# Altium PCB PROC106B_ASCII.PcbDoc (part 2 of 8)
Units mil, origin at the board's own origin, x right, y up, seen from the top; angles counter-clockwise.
Board outline 4498.18 x 1060.53 mil, 8 copper layers (Top Layer, GND1, Sig1, PWR1, PWR2, Sig2, GND2, Bottom Layer), stack 69.602 mil thick; 439 components, 327 nets, 1548 pads, 843 vias.
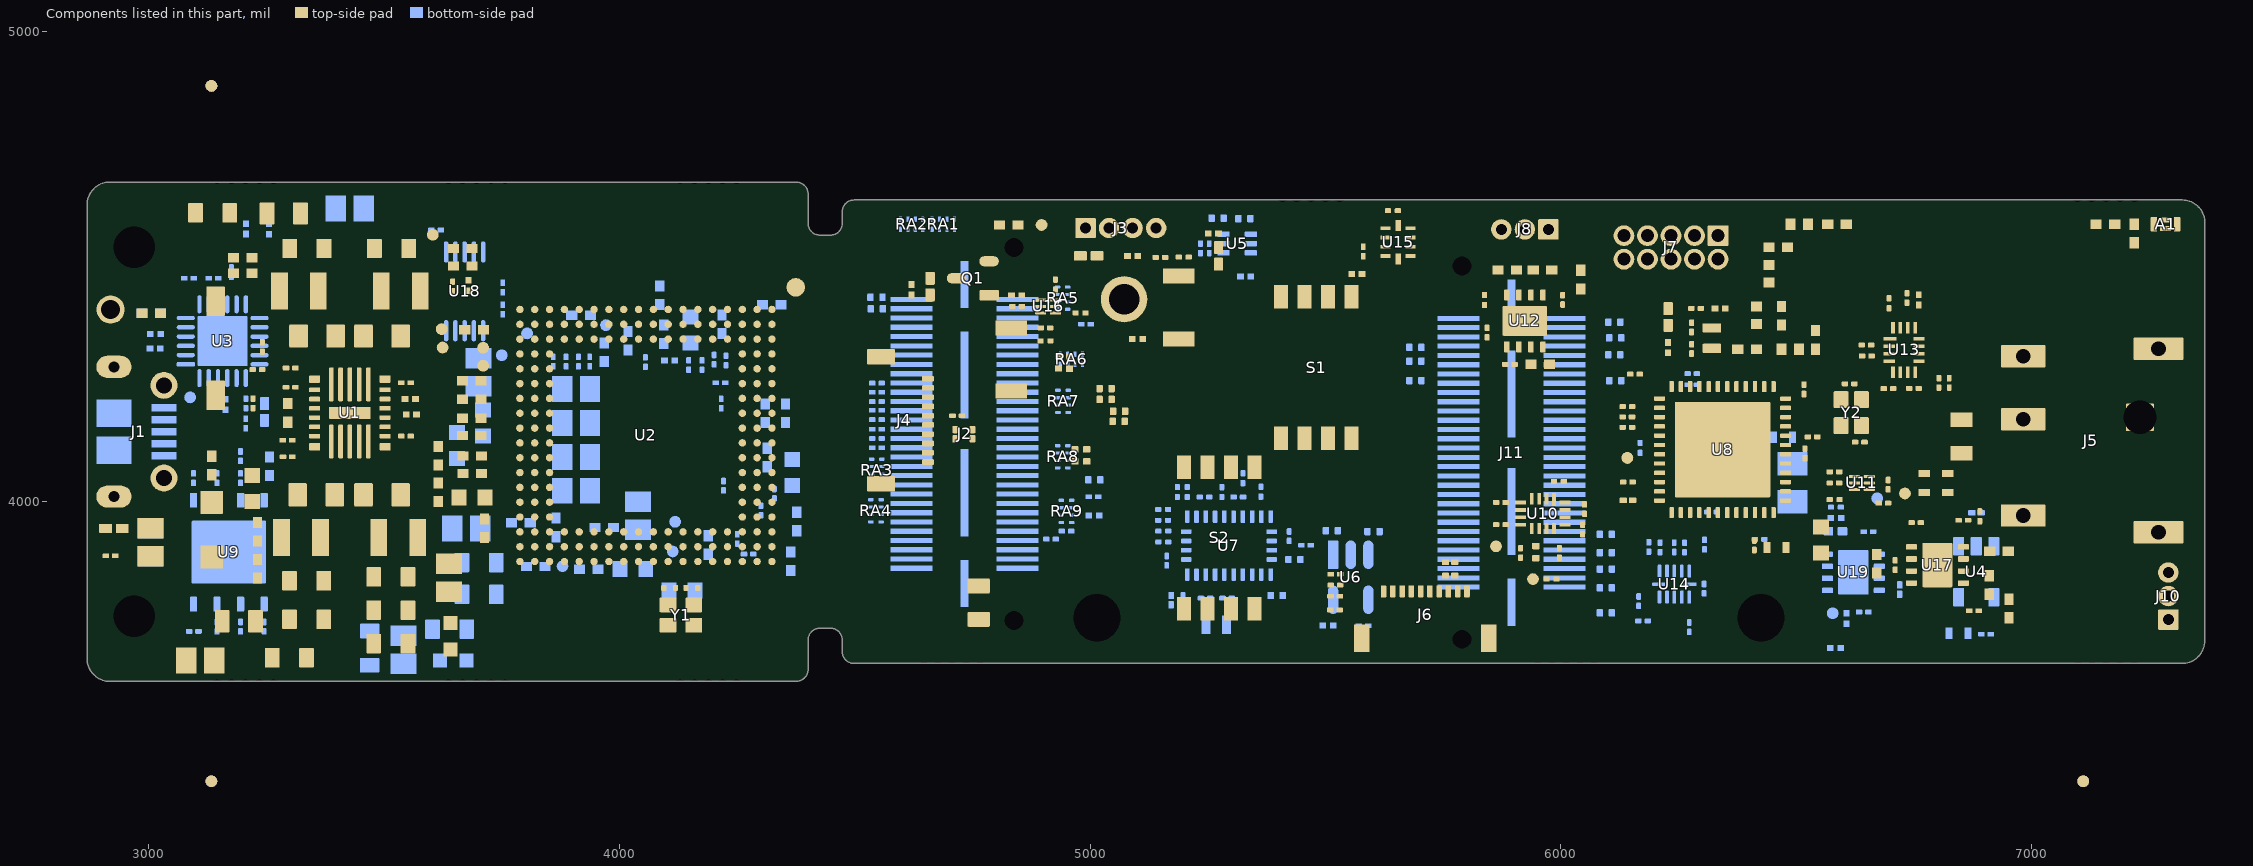
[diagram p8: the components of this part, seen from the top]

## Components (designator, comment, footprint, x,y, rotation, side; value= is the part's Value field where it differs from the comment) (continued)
C125 "CL03A103KA3NNNC" FP-CL03A103KA3NNNC_0201-IPC_C 5252.95,4538.7 r270 bottom
C126 "GCM155R71C104KA55D" 0402L 3691.38,4365.53 r180 top
C127 "GRM033R6YA104KE14D" "FP-GRM033R6YA104KE14D_0201 (0603 Metric)-IPC_C" 6653.18,3936.75 r180 bottom
C128 "GRM033R6YA104KE14D" "FP-GRM033R6YA104KE14D_0201 (0603 Metric)-IPC_C" 6643.28,3766.12 r180 bottom
C129 "CL03A105MO3NRNH" FP-CL03A105MO3NRNH_0201-IPC_C 6719.58,3813.74 r270 bottom
C130 "GCM155R71C104KA55D" 0402L 3967.83,4318.05 r90 bottom
C131 "CGA4J1X7T0J226M125AC" FP-CGA4J1X7T0J226M125AC_0805-MFG 3469.55,3689.64 r90 bottom
D1 "NRVB230LSFT1G" FP-NRVB230LSFT1G_SOD-123F-MFG 3134.01,3940.99 r90 top
Designator1 "Comment" MHNP_M2_PANHEAD_PHILLIPS 2983.52,4883.72 r0 top
Designator1_1 "BRAKE_WAY_HOLES1X2" BRAKE_WAY_HOLES1X2 3205.41,3572.64 r180 bottom
Designator1_2 "Comment" MHNP_M2_PANHEAD_PHILLIPS 2969.58,4541.42 r0 top
Designator2 "BRAKE_WAY_HOLES1X2" BRAKE_WAY_HOLES1X2 4188.97,4725.69 r180 top
Designator2_1 "BRAKE_WAY_HOLES1X2" BRAKE_WAY_HOLES1X2 6010.52,3609.79 r180 bottom
Designator3 "BRAKE_WAY_HOLES1X2" BRAKE_WAY_HOLES1X2 3697.19,4725.69 r180 top
Designator3_2 "BRAKE_WAY_HOLES1X2" BRAKE_WAY_HOLES1X2 5469.11,4687.74 r0 bottom
Designator4 "BRAKE_WAY_HOLES1X2" BRAKE_WAY_HOLES1X2 4706.5,3609.79 r0 top
Designator4_1 "BRAKE_WAY_HOLES1X2" BRAKE_WAY_HOLES1X2 3697.19,3572.64 r180 bottom
Designator5 "BRAKE_WAY_HOLES1X2" BRAKE_WAY_HOLES1X2 7157.87,4687.69 r180 top
Designator5_1 "BRAKE_WAY_HOLES1X2" BRAKE_WAY_HOLES1X2 7157.6,3609.79 r180 bottom
Designator5_2 "BRAKE_WAY_HOLES1X2" BRAKE_WAY_HOLES1X2 4188.97,3572.64 r180 bottom
Designator6 "Comment" MHNP_M2_PANHEAD_PHILLIPS 7259.4,4883.72 r0 top
Designator7 "Comment" MHNP_M2_PANHEAD_PHILLIPS 2983.52,3406.7 r0 top
Designator7_1 "Comment" MHNP_M2_PANHEAD_PHILLIPS 2969.58,3756.91 r0 top
Designator8 "Comment" MHNP_M2_PANHEAD_PHILLIPS 7259.4,3406.7 r0 top
Designator10 "BRAKE_WAY_HOLES1X2" BRAKE_WAY_HOLES1X2 3205.41,4725.69 r180 top
Designator22_1 "Comment" MHNP_2-5 6425,3754.06 r0 bottom
Designator23 "Comment" MHNP_2-5 5014.62,3754.06 r0 bottom
FID1 "Fiducial" FIDUCIAL6.4-20 3133.52,3406.7 r0 top
FID2 "Fiducial" FIDUCIAL6.4-20 3133.52,4883.72 r0 top
FID3 "Fiducial" FIDUCIAL6.4-20 7109.4,3406.7 r0 top
FID4 "Fiducial" FIDUCIAL6.4-20 7109.4,3406.7 r180 bottom
FID5 "Fiducial" FIDUCIAL6.4-20 3133.52,4883.72 r180 bottom
FID6 "Fiducial" FIDUCIAL6.4-20 3133.52,3406.7 r180 bottom
FL2 "BLM15PD300SZ1D" 0402L 3134.06,4077.41 r270 top
FL3 "BLM15PD300SZ1D" 0402L 6670.79,3868.56 r90 top
FL12 "BLM15PD300SZ1D" 0402L 5955.92,4292.41 r0 top
FL22 "BLM15PD300SZ1D" 0402L 4827.36,4588.36 r0 top
J1 "105017-0001" CONN_105017-0001 2979.51,4149.15 r90 bottom
J2 "QSH-030-01-L-D-A" Samtec_QSH-030-01-X-D-A 4733.36,4144.5 r0 bottom locked
J3 "M50-3930442" FP-M50-3930442_HDR4-RECOMMENDED_LAND_PATTERN 5065.29,4621.12 r0 bottom
J4 "51441-1093" FP-51441-1093_CONN_SMD_FFC-0 4585.45,4173.34 r270 top locked
J5 "PJ-051AH" CUI_PJ-051AH 7229.96,4179.69 r0 top
J6 "51441-1093" FP-51441-1093_CONN_SMD_FFC-0 5711.91,3740.17 r0 top
J7 "GRPB052MWCN-RC" FP-GRPB052MWCN-RC_HDR10-MFG 6233.84,4610.83 r180 top
J8 "M50-3930342" FP-M50-3930342_HDR3-MFG 5923.44,4618.25 r180 top
J10 "M50-3930342" FP-M50-3930342_HDR3-MFG 7329.6,3800 r90 top
J11 "QSH-030-01-L-D-A" Samtec_QSH-030-01-X-D-A 5895.12,4104.5 r180 bottom locked
L1 "LQG15HS2N4S02D" IND_LQG15H 6487.22,4324.41 r0 top
L2 "DFE252012PD-R47M" DFE252012P 3535.79,4447.85 r180 top
L3 "DFE252012PD-R47M" DFE252012P 3319.27,4447.85 r0 top
L4 "DFE252012PD-R47M" DFE252012P 3530.36,3924.63 r180 top
L5 "DFE252012PD-R47M" DFE252012P 3323.75,3924.63 r0 top
L6 "LQG15HS2N4S02D" IND_LQG15H 6415.18,4396.46 r90 top
L7 "MLZ2012N6R8LT000" 0805_HV 6491.96,4040.83 r90 bottom
L8 "BLM18HE152SN1D" 0603L 6552.57,3919.1 r90 top
L9 "LQG15HS2N0S02D" IND_LQG15H 6441.85,4484.72 r90 top
L10 "LQG15HS2N0S02D" IND_LQG15H 6506.46,4589.83 r0 top
L11 "MPZ2012S101ATD25" FP-MPZ2012S101ATD25_0805-MFG 3191.81,3746.61 r180 top
L12 "BLM18KG121TH1D" 0603_HV 3641.39,3714.72 r90 top
L13 "MPZ2012S101ATD25" FP-MPZ2012S101ATD25_0805-MFG 3287.13,4612.77 r0 top
L14 "BLM18KG121TH1D" 0603_HV 3647.19,3662.86 r180 bottom
L15 "MPZ2012S101ATD25" FP-MPZ2012S101ATD25_0805-MFG 6850.96,4138.99 r270 top
L16 "MPZ2012S101ATD25" FP-MPZ2012S101ATD25_0805-MFG 4763.29,3786.02 r270 top
LD1 "APHHS1005CGCK" APHHS1005_Green 2926.36,3943.79 r0 top
LD2 "APHHS1005CGCK" APHHS1005_Green 5272.84,4522.72 r270 top
LD3 "APHHS1005CGCK" APHHS1005_Green 4997.02,4522.72 r0 top
LD4 "APHHS1005CGCK" APHHS1005_Green 3246.44,4191.13 r270 bottom
LD5 "APHHS1005CGCK" APHHS1005_Green 4660.11,4457.37 r90 top
LD6 "APHHS1005CGCK" APHHS1005_Green 6227.85,4392.84 r90 top
Q1 "BSS123-7-F" FP-BSS123-7-F_SOT23-IPC_C 4750.81,4475.09 r180 top
R1 "RR0306P-103-D" FP-RR0306P-103-D_0201-IPC_C#1 5643.17,4618.56 r180 top
R2 "ERJ-1GN0R00C" 0201L 4106.92,4300.76 r180 bottom
R3 "ERA-1AEB103C" FP-ERA-1AEB103C_0201-IPC_C 4274.79,3889.16 r180 bottom
R4 "ERJ-1GNF1003C" FP-ERJ-1GNF1003C_0201-IPC_C 3752.34,4408.84 r270 bottom
R5 "ERJ-1GNF1003C" FP-ERJ-1GNF1003C_0201-IPC_C 3752.34,4455.46 r90 bottom
R6 "ERJ-1GNF33R2C" FP-ERJ-1GNF33R2C_0201-IPC_C 3095.35,4050.45 r270 bottom
R7 "ERA-1AEB103C" FP-ERA-1AEB103C_0201-IPC_C 4329.25,4017.43 r270 bottom
R8 "ERA-1AEB103C" FP-ERA-1AEB103C_0201-IPC_C 4221.23,4034.41 r270 bottom
R9 "ERJ-1GNF1003C" FP-ERJ-1GNF1003C_0201-IPC_C 4250.53,3921.56 r270 bottom
R10 "AC0201FR-0720RL" FP-AC0201FR-0720RL_0201-IPC_C 4917.01,3921 r180 bottom
R11 "AC0201FR-0720RL" FP-AC0201FR-0720RL_0201-IPC_C 4950.01,3937.94 r180 bottom
R12 "RC0201JR-070RL" "FP-RC0201JR-070RL_0201 (0603 Metric)-MFG" 4546.15,4434.59 r180 bottom
R13 "RC0201JR-07220RL" 0201L 5261.81,4570.64 r0 top
R14 "RC0201JR-070RL" "FP-RC0201JR-070RL_0201 (0603 Metric)-MFG" 4547.12,4410.25 r180 bottom
R15 "ERJ-1GNJ221C" FP-ERJ-1GNJ221C_0201-IPC_C 3206.52,4166.71 r90 bottom
R16 "RC0201FR-077K87L" 0201L 5566.39,4484.46 r180 top
R17 "RC0201JR-07220RL" 0201L 6227.85,4327.64 r90 top
R18 "RR0306P-103-D" FP-RR0306P-103-D_0201-IPC_C#1 5362.78,4021.8 r270 bottom
R19 "ERA-1AEB103C" FP-ERA-1AEB103C_0201-IPC_C 3610.73,4577.6 r180 bottom
R20 "RR0306P-103-D" FP-RR0306P-103-D_0201-IPC_C#1 6584.18,3988.94 r180 bottom
R21 "ERA-1AEB103C" FP-ERA-1AEB103C_0201-IPC_C 3859.46,4298.05 r270 bottom
R22 "ERA-1AEB103C" FP-ERA-1AEB103C_0201-IPC_C 3886.73,4298.05 r270 bottom
R23 "ERA-1AEB103C" FP-ERA-1AEB103C_0201-IPC_C 3913.05,4298.05 r270 bottom
R24 "CRCW0402200RFKEDHP" FP-CRCW0402200RFKEDHP_0402-IPC_C 6583.18,3937.46 r180 bottom
R25 "ERJ-1GNF4991C" FP-ERJ-1GNF4991C_0201-IPC_C 3301.93,4243.48 r180 top
R26 "ERJ-1GNF4991C" FP-ERJ-1GNF4991C_0201-IPC_C 3295.24,4131.09 r180 top
R27 "RC0201JR-07510RL" 0201L 6606.39,3752.54 r90 bottom
R28 "ERJ-1GN0R00C" 0201L 3555.87,4218.48 r180 top
R29 "CRCW0201100KFKED" 0201L 6584.18,3965.94 r180 bottom
R30 "RC0201JR-070RL" "FP-RC0201JR-070RL_0201 (0603 Metric)-MFG" 5946.67,3893.52 r90 top
R31 "ERJ-1GN0R00C" 0201L 5008.05,3971.4 r180 bottom
R32 "ERJ-1GN0R00C" 0201L 3558.22,4185.79 r180 top
R33 "ERJ-1GNF4991C" FP-ERJ-1GNF4991C_0201-IPC_C 3295.5,4095.96 r180 top
R34 "ERJ-1GNF4991C" FP-ERJ-1GNF4991C_0201-IPC_C 3546.86,4253.13 r0 top
R35 "ERA-1AEB103C" FP-ERA-1AEB103C_0201-IPC_C 3301.93,4284.61 r180 top
R36 "ERA-1AEB103C" FP-ERA-1AEB103C_0201-IPC_C 3546.86,4139.79 r0 top
R37 "ERJ-1GNF1003C" FP-ERJ-1GNF1003C_0201-IPC_C 5007.04,4011.07 r180 bottom
R38 "RC0201FR-074K99L" 0201L 5330.47,4478.82 r180 bottom
R39 "ERJ-1GNJ511C" FP-ERJ-1GNJ511C_0201-IPC_C 2919.28,3885.59 r180 top
R40 "ERJ-1GNF4991C" FP-ERJ-1GNF4991C_0201-IPC_C 3175.78,4488.13 r270 bottom
R41 "ERJ-1GN0R00C" 0201L 3013.92,4326.25 r180 bottom
R42 "RC0201JR-07220RL" 0201L 5090.29,4522.72 r0 top
R43 "ERA-1AEB103C" FP-ERA-1AEB103C_0201-IPC_C 3245.35,3734.95 r270 bottom
R44 "ERA-1AEB103C" FP-ERA-1AEB103C_0201-IPC_C 3095.98,3724.94 r180 bottom
R45 "ERA-1AEB103C" FP-ERA-1AEB103C_0201-IPC_C 3195.34,4097.11 r90 bottom
R46 "ERJ-1GNF33R2C" FP-ERJ-1GNF33R2C_0201-IPC_C 3195.35,3734.95 r90 bottom
R47 "ERJ-1GNF33R2C" FP-ERJ-1GNF33R2C_0201-IPC_C 3145.35,4050.45 r270 bottom
R48 "ERJ-1GNF33R2C" FP-ERJ-1GNF33R2C_0201-IPC_C 3145.35,3734.95 r90 bottom
R49 "ERJ-1GNF33R2C" FP-ERJ-1GNF33R2C_0201-IPC_C 3195.35,4050.45 r270 bottom
R50 "ERJ-1GNJ102C" FP-ERJ-1GNJ102C_0201-IPC_C 3241.63,4329.43 r90 top
R51 "RC0201JR-070RL" "FP-RC0201JR-070RL_0201 (0603 Metric)-MFG" 5327.6,4601.84 r0 bottom
R52 "ERJ-1GNF1961C" FP-ERJ-1GNF1961C_0201-IPC_C 3231.08,4281.06 r0 top
R53 "CRCW04023R83FKED" 0402L 3667.5,4501.24 r180 top
R54 "CRCW04023R83FKED" 0402L 3200.34,4485.56 r0 top
R55 "CRCW04023R83FKED" 0402L 3615.39,4020.22 r270 top
R56 "CRCW04023R83FKED" 0402L 3231.35,3858.36 r270 top
R57 "RC0201JR-070RL" "FP-RC0201JR-070RL_0201 (0603 Metric)-MFG" 5270.8,4602.69 r0 bottom
R58 "RC0201JR-070RL" "FP-RC0201JR-070RL_0201 (0603 Metric)-MFG" 5008.99,4046.94 r180 bottom
R59 "ERA-1AEB103C" FP-ERA-1AEB103C_0201-IPC_C 3936.98,4298.05 r270 bottom
R60 "ERJ-1GN0R00C" 0201L 3014.55,4356.6 r180 bottom
R61 "ERJ-1GN0R00C" 0201L 3163.55,4206.75 r90 bottom
R62 "ERJ-1GN0R00C" 0201L 3206.51,4580.21 r270 bottom
R63 "ERJ-1GN0R00C" 0201L 3255.87,4579.81 r270 bottom
R64 "ERJ-1GNF4991C" FP-ERJ-1GNF4991C_0201-IPC_C 3086.14,4475.15 r0 bottom
R65 "ERA-1AEB103C" FP-ERA-1AEB103C_0201-IPC_C 3137.8,4475.15 r180 bottom
R66 "RC0201JR-070RL" "FP-RC0201JR-070RL_0201 (0603 Metric)-IPC_C" 4991.42,4377.56 r0 bottom
R67 "RC0201JR-070RL" "FP-RC0201JR-070RL_0201 (0603 Metric)-MFG" 5513.34,3938.91 r0 bottom
R68 "RC0201JR-070RL" "FP-RC0201JR-070RL_0201 (0603 Metric)-MFG" 5601.88,3937.06 r180 bottom
R69 "RC0201FR-074K99L" 0201L 5505.11,3737.11 r180 bottom
R70 "RC0201JR-070RL" "FP-RC0201JR-070RL_0201 (0603 Metric)-MFG" 5434,3877.69 r0 bottom
R71 "RC0201JR-070RL" "FP-RC0201JR-070RL_0201 (0603 Metric)-MFG" 5396.26,3801.26 r0 bottom
R72 "RC0201JR-070RL" "FP-RC0201JR-070RL_0201 (0603 METRIC)-IPC_C" 5422.76,3927.24 r270 bottom
R73 "RC0201JR-070RL" "FP-RC0201JR-070RL_0201 (0603 METRIC)-IPC_C" 5458.86,3908 r180 bottom
R74 "RC0201JR-070RL" "FP-RC0201JR-070RL_0201 (0603 METRIC)-IPC_C" 6581.1,4063.92 r0 top
R75 "ERJ-1GNJ102C" FP-ERJ-1GNJ102C_0201-IPC_C 4300.76,3981.67 r270 bottom
R76 "RC0201JR-070RL" "FP-RC0201JR-070RL_0201 (0603 METRIC)-IPC_C" 6210.78,3903.45 r90 bottom
R77 "RR0306P-103-D" FP-RR0306P-103-D_0201-IPC_C#1 5185.3,4021 r270 bottom
R78 "RR0306P-103-D" FP-RR0306P-103-D_0201-IPC_C#1 5155,3984 r0 bottom
R79 "ERJ-1GNF4701C" FP-ERJ-1GNF4701C_0201-IPC_C 6304.11,3815.65 r270 bottom
R80 "RR0306P-103-D" FP-RR0306P-103-D_0201-IPC_C#1 5155.48,3915 r0 bottom
R81 "RR0306P-103-D" FP-RR0306P-103-D_0201-IPC_C#1 5324.41,4050.42 r270 bottom
R82 "RR0306P-103-D" FP-RR0306P-103-D_0201-IPC_C#2 5279.72,4021 r270 bottom
R83 "ERA-1AEB103C" FP-ERA-1AEB103C_0201-IPC_C 4055.26,4296.88 r270 bottom
R84 "ERA-1AEB103C" FP-ERA-1AEB103C_0201-IPC_C 4216.3,4208.84 r90 bottom
R85 "ERA-1AEB103C" FP-ERA-1AEB103C_0201-IPC_C 3645.85,4457.99 r270 top
R86 "RC0201JR-070RL" "FP-RC0201JR-070RL_0201 (0603 METRIC)-IPC_C" 6141.03,4180.57 r0 top
R87 "RC0201JR-070RL" "FP-RC0201JR-070RL_0201 (0603 METRIC)-IPC_C" 6141.18,4202.46 r0 top
R88 "AC0201FR-0720RL" FP-AC0201FR-0720RL_0201-IPC_C 4547.27,4114.97 r0 bottom
R89 "CRCW0201100KFKED" 0201L 6338.19,4411.08 r0 top
R90 "RC0201JR-070RL" "FP-RC0201JR-070RL_0201 (0603 METRIC)-IPC_C" 6278.99,4249 r0 bottom
R91 "RC0201JR-070RL" "FP-RC0201JR-070RL_0201 (0603 METRIC)-IPC_C" 6422.16,3920.53 r180 bottom
R92 "CRCW0201100KFKED" 0201L 6583.22,3689.74 r0 bottom
R93 "RR0306P-103-D" FP-RR0306P-103-D_0201-IPC_C#1 5206.3,4021 r90 bottom
R94 "RR0306P-103-D" FP-RR0306P-103-D_0201-IPC_C#1 5995.7,4043.69 r0 top
R95 "RR0306P-103-D" FP-RR0306P-103-D_0201-IPC_C#1 5979.95,3836.09 r0 top
R96 "RR0306P-103-D" FP-RR0306P-103-D_0201-IPC_C#1 5155.48,3938 r180 bottom
R97 "RC0201JR-070RL" "FP-RC0201JR-070RL_0201 (0603 METRIC)-IPC_C" 5314.73,4010.48 r0 bottom
R98 "RR0306P-103-D" FP-RR0306P-103-D_0201-IPC_C#1 5155,3961 r180 bottom
R99 "RC0201JR-070RL" "FP-RC0201JR-070RL_0201 (0603 METRIC)-IPC_C" 5996.83,3891.7 r270 top
R100 "RC0201JR-070RL" "FP-RC0201JR-070RL_0201 (0603 METRIC)-IPC_C" 5872.42,3998.82 r0 top
R101 "RC0201JR-070RL" "FP-RC0201JR-070RL_0201 (0603 METRIC)-IPC_C" 6046.19,3941.56 r270 top
R102 "RC0201JR-070RL" "FP-RC0201JR-070RL_0201 (0603 METRIC)-IPC_C" 6278.99,4272.45 r0 bottom
R103 "ERJ-1GN0R00C" 0201L 3679.35,4459.54 r270 top
R104 "RR0306P-103-D" FP-RR0306P-103-D_0201-IPC_C#1 6581.47,4005 r180 top
R105 "RC0201JR-070RL" "FP-RC0201JR-070RL_0201 (0603 METRIC)-IPC_C" 6685.03,3997.34 r180 top
R106 "RC0201JR-070RL" "FP-RC0201JR-070RL_0201 (0603 METRIC)-IPC_C" 6695.04,4036.52 r90 top
R107 "RC0201JR-07510RL" 0201L 4620.57,4450.68 r270 top
R108 "RC0201JR-07510RL" 0201L 4843.99,4439.06 r180 top
R110 "RR0306P-103-D" FP-RR0306P-103-D_0201-IPC_C#1 6168.27,4114.75 r270 bottom
R111 "RC0201JR-07220RL" 0201L 5100.51,4345.88 r180 top
R112 "RC0201JR-070RL" "FP-RC0201JR-070RL_0201 (0603 METRIC)-IPC_C" 5872.42,3951.7 r0 top
R113 "RC0201JR-070RL" "FP-RC0201JR-070RL_0201 (0603 METRIC)-IPC_C" 5914.31,3891.7 r90 top
R114 "CRCW040261R9FKED" 0402L 6930.63,3895.33 r180 top
R115 "RC0201JR-070RL" "FP-RC0201JR-070RL_0201 (0603 Metric)-IPC_C" 6854.79,3961 r0 top
R116 "RC0201JR-070RL" "FP-RC0201JR-070RL_0201 (0603 Metric)-IPC_C" 6754.79,3956 r0 top
R117 "CRCW040261R9FKED" 0402L 6909.66,3823.52 r270 top
R118 "RR0306P-103-D" FP-RR0306P-103-D_0201-IPC_C#1 6696.81,4422 r90 top
R119 "CRCW040261R9FKED" 0402L 5885.96,4492.77 r0 top
R120 "RC0201JR-070RL" "FP-RC0201JR-070RL_0201 (0603 Metric)-IPC_C" 6802.81,4252.99 r90 top
R121 "RC0201JR-070RL" "FP-RC0201JR-070RL_0201 (0603 METRIC)-IPC_C" 6649.04,4333.23 r180 top
R122 "RR0306P-103-D" FP-RR0306P-103-D_0201-IPC_C#1 5837.64,4429.06 r270 top
R123 "RC0201JR-070RL" "FP-RC0201JR-070RL_0201 (0603 METRIC)-IPC_C" 5843.14,4359.71 r90 top
R124 "RR0306P-103-D" FP-RR0306P-103-D_0201-IPC_C#1 4905.31,4342.12 r0 top
R125 "RR0306P-103-D" FP-RR0306P-103-D_0201-IPC_C#1 5198.85,4520.03 r180 top
R126 "CRCW040261R9FKED" 0402L 5960.92,4492.48 r0 top
R127 "RC0201JR-070RL" "FP-RC0201JR-070RL_0201 (0603 METRIC)-IPC_C" 6649.8,4310 r0 top
R128 "RC0201JR-070RL" "FP-RC0201JR-070RL_0201 (0603 METRIC)-IPC_C" 6695.72,4240.71 r180 top
R129 "RC0201JR-070RL" "FP-RC0201JR-070RL_0201 (0603 METRIC)-IPC_C" 5149.26,4519.45 r180 top
R130 "AC0201FR-0720RL" FP-AC0201FR-0720RL_0201-IPC_C 4547.27,4134.63 r0 bottom
R131 "RC0201JR-070RL" "FP-RC0201JR-070RL_0201 (0603 METRIC)-IPC_C" 6321.17,3978.41 r180 bottom
R132 "AC0201FR-0720RL" FP-AC0201FR-0720RL_0201-IPC_C 4547.27,4154.34 r0 bottom
R133 "AC0201FR-0720RL" FP-AC0201FR-0720RL_0201-IPC_C 4547.27,4174.75 r0 bottom
R134 "RR0306P-103-D" FP-RR0306P-103-D_0201-IPC_C#1 6889.73,3969.51 r90 top
R135 "AC0201FR-0720RL" FP-AC0201FR-0720RL_0201-IPC_C 4547.27,4194.78 r0 bottom
R136 "RC0201JR-070RL" "FP-RC0201JR-070RL_0201 (0603 Metric)-IPC_C" 6749.82,4241 r0 top
R137 "AC0201FR-0720RL" FP-AC0201FR-0720RL_0201-IPC_C 4547.27,4213.11 r0 bottom
R138 "AC0201FR-0720RL" FP-AC0201FR-0720RL_0201-IPC_C 4547.27,4233.08 r0 bottom
R139 "RC0201JR-070RL" "FP-RC0201JR-070RL_0201 (0603 Metric)-IPC_C" 6824.81,4252.99 r270 top
R140 "AC0201FR-0720RL" FP-AC0201FR-0720RL_0201-IPC_C 4547.27,4252.4 r0 bottom
R141 "RC0201FR-074K99L" 0201L 6760.03,4429.26 r90 top
R142 "RC0201JR-070RL" "FP-RC0201JR-070RL_0201 (0603 Metric)-MFG" 4992.71,4098.76 r270 top
R143 "RC0201JR-070RL" "FP-RC0201JR-070RL_0201 (0603 Metric)-MFG" 4967.77,4098.76 r270 top
R144 "RC0201JR-070RL" "FP-RC0201JR-070RL_0201 (0603 Metric)-MFG" 5061.58,4192.66 r0 top
R145 "RC0201JR-070RL" "FP-RC0201JR-070RL_0201 (0603 Metric)-MFG" 5060.48,4171.22 r0 top
R146 "RC0201JR-070RL" "FP-RC0201JR-070RL_0201 (0603 Metric)-MFG" 5032.8,4217.79 r0 top
R147 "RC0201JR-070RL" "FP-RC0201JR-070RL_0201 (0603 Metric)-MFG" 5032.8,4240.79 r0 top
R148 "RC0201JR-070RL" "FP-RC0201JR-070RL_0201 (0603 Metric)-MFG" 4932.76,4296.62 r90 top
R149 "RC0201JR-070RL" "FP-RC0201JR-070RL_0201 (0603 Metric)-MFG" 4956.17,4295.87 r90 top
R150 "RC0201JR-070RL" "FP-RC0201JR-070RL_0201 (0603 Metric)-MFG" 6113.61,4381.76 r0 bottom
R151 "RC0201JR-070RL" "FP-RC0201JR-070RL_0201 (0603 Metric)-MFG" 6115.41,4348.48 r0 bottom
R152 "RC0201JR-070RL" "FP-RC0201JR-070RL_0201 (0603 Metric)-MFG" 5690.93,4328.4 r0 bottom
R153 "RC0201JR-070RL" "FP-RC0201JR-070RL_0201 (0603 Metric)-MFG" 6113.32,4312.59 r0 bottom
R154 "RC0201JR-070RL" "FP-RC0201JR-070RL_0201 (0603 Metric)-MFG" 5690.93,4298.93 r0 bottom
R155 "RC0201JR-070RL" "FP-RC0201JR-070RL_0201 (0603 Metric)-MFG" 6115.55,4257.57 r0 bottom
R157 "RC0201JR-070RL" "FP-RC0201JR-070RL_0201 (0603 Metric)-MFG" 5690.93,4257.72 r0 bottom
R158 "ERJ-1GNF8252C" FP-ERJ-1GNF8252C_0201-IPC_C 4175.56,4290.74 r270 bottom
R159 "ERJ-1GNJ751C" FP-ERJ-1GNJ751C_0201-IPC_C 4201.23,4302.15 r90 bottom
R160 "RC0201JR-070RL" "FP-RC0201JR-070RL_0201 (0603 METRIC)-IPC_C" 6262.64,3903.15 r90 bottom
R161 "RC0201JR-070RL" "FP-RC0201JR-070RL_0201 (0603 METRIC)-IPC_C" 6141.18,4158.46 r0 top
R166 "RC0201JR-070RL" "FP-RC0201JR-070RL_0201 (0603 METRIC)-IPC_C" 6240.62,3903.59 r90 bottom
R168 "RC0201JR-070RL" "FP-RC0201JR-070RL_0201 (0603 METRIC)-IPC_C" 6186.75,3904.39 r90 bottom
R170 "ERJ-1GNF8252C" FP-ERJ-1GNF8252C_0201-IPC_C 4214.74,4253.13 r180 bottom
R171 "ERJ-1GNJ751C" FP-ERJ-1GNJ751C_0201-IPC_C 4226.45,4300.41 r90 bottom
R172 "ERJ-1GNF8252C" FP-ERJ-1GNF8252C_0201-IPC_C 3206.71,4209.45 r270 bottom
R174 "ERJ-1GNF7871C" FP-ERJ-1GNF7871C_0201-IPC_C 4147.23,4290.74 r270 bottom
R176 "ERJ-1GNF7871C" FP-ERJ-1GNF7871C_0201-IPC_C 3221.71,4209.45 r270 top
R177 "RR0306P-103-D" FP-RR0306P-103-D_0201-IPC_C#1 4979.62,4401.5 r180 top
R178 "RR0306P-103-D" FP-RR0306P-103-D_0201-IPC_C#1 4926.29,4461.7 r270 top
R180 "ERJ-1GNF4701C" FP-ERJ-1GNF4701C_0201-IPC_C 6165.19,3789.15 r270 bottom
R181 "ERJ-1GNF4701C" FP-ERJ-1GNF4701C_0201-IPC_C 5520.05,3770.65 r180 top
R182 "RC0201JR-070RL" "FP-RC0201JR-070RL_0201 (0603 METRIC)-IPC_C" 4717.71,4183.18 r180 top
R183 "RC0201JR-070RL" "FP-RC0201JR-070RL_0201 (0603 METRIC)-IPC_C" 5520.61,3799.62 r180 top
R184 "RC0201JR-070RL" "FP-RC0201JR-070RL_0201 (0603 METRIC)-IPC_C" 5521.16,3823.28 r180 top
R185 "RC0201JR-070RL" "FP-RC0201JR-070RL_0201 (0603 METRIC)-IPC_C" 5521,3846.49 r180 top
R186 "RC0201JR-070RL" "FP-RC0201JR-070RL_0201 (0603 Metric)-MFG" 6095.54,3931.22 r0 bottom
R187 "RC0201JR-070RL" "FP-RC0201JR-070RL_0201 (0603 Metric)-MFG" 6095.54,3892.26 r0 bottom
R188 "RC0201JR-070RL" "FP-RC0201JR-070RL_0201 (0603 Metric)-MFG" 6095.54,3857.41 r0 bottom
R189 "RC0201JR-070RL" "FP-RC0201JR-070RL_0201 (0603 Metric)-MFG" 6095.54,3817.56 r0 bottom
R190 "RC0201JR-070RL" "FP-RC0201JR-070RL_0201 (0603 Metric)-MFG" 6095.54,3764.53 r0 bottom
RA1 "EXB-18VR000X" FP-EXB-18VR000X_0502-MFG 4688.09,4589.75 r0 bottom
RA2 "EXB-18VR000X" FP-EXB-18VR000X_0502-MFG 4620.86,4589.75 r0 bottom
RA3 "EXB-18VR000X" FP-EXB-18VR000X_0502-MFG 4546.77,4067.23 r90 bottom
RA4 "EXB-18VR000X" FP-EXB-18VR000X_0502-MFG 4545.1,3981.11 r90 bottom
RA5 "EXB-18VR000X" FP-EXB-18VR000X_0502-MFG 4941.51,4432.71 r90 bottom locked
RA6 "EXB-18VR000X" FP-EXB-18VR000X_0502-MFG 4960.21,4302.91 r0 bottom
RA7 "EXB-18VR000X" FP-EXB-18VR000X_0502-MFG 4942.52,4213.65 r90 bottom locked
RA8 "EXB-18VR000X" FP-EXB-18VR000X_0502-MFG 4941.86,4095.87 r90 bottom locked
RA9 "EXB-18VR000X" FP-EXB-18VR000X_0502-MFG 4949.85,3979.76 r90 bottom locked
S1 "218-4LPST" SW_218-4LPST 5480.37,4285.46 r90 top
S2 "218-4LPST" SW_218-4LPST 5274.37,3923.46 r90 top locked
S3 "CHS-01TA" FP-CHS-01TA_SMT_SW_5MM4_2MM5-MFG 3142.31,4326.42 r90 top
SW2 "B3U-1000P" SW_B3U-1000P 4832.84,4302.77 r270 top
SW3 "B3U-1000P" SW_B3U-1000P 5188.73,4412.81 r270 top
TP2 "TESTPOINT" TP_25MIL-SMT 4113.44,3894.78 r180 bottom
TP3 "TESTPOINT" TP_25MIL-SMT 4118.39,3957.8 r180 bottom
TP4 "TESTPOINT" TP_25MIL-SMT 6671.71,4007.65 r180 bottom
TP5 "TESTPOINT" TP_25MIL-SMT 3603.84,4567.52 r180 top
TP6 "TESTPOINT" TP_25MIL-SMT 3750.12,4311.58 r90 bottom
TP7 "TESTPOINT" TP_25MIL-SMT 3804,4358 r0 bottom
TP8 "TESTPOINT" TP_25MIL-SMT 3710.6,4327.53 r0 top
TP9 "TESTPOINT" TP_25MIL-SMT 3710.6,4289.4 r0 top
TP10 "TESTPOINT" TP_25MIL-SMT 6577.18,3763.46 r270 bottom
TP11 "TP_SM_1MM" TP_SM_1MM 4374.76,4455.87 r180 top
TP12 "TESTPOINT" TP_VIA_060RND040 2919.28,4408.64 r90 top
TP13 "TESTPOINT" TP_25MIL-SMT 4896.84,4588.36 r270 top
TP14 "TESTPOINT" TP_25MIL-SMT 3971.52,4375.57 r270 bottom
TP15 "TESTPOINT" TP_25MIL-SMT 6730.81,4018 r90 top
TP16 "TESTPOINT" TP_25MIL-SMT 6141.18,4093.46 r180 top
TP17 "TESTPOINT" TP_25MIL-SMT 3879.25,3863.39 r180 bottom
TP18 "TESTPOINT" TP_25MIL-SMT 3622.56,4367.08 r180 top
TP19 "TESTPOINT" TP_25MIL-SMT 3624.53,4327.96 r180 top
TP20 "4953" FP-4953_HDR1-MFG 5072.16,4430.47 r180 bottom locked
TP26 "TESTPOINT" TP_25MIL-SMT 3088.22,4222.02 r0 bottom
TP27 "TESTPOINT" TP_25MIL-SMT 5862.18,3905.74 r270 top
TP46 "TESTPOINT" TP_25MIL-SMT 5940.71,3836.09 r270 top
U1 "LP87524JRNFRQ1" RNF0026C 3427.48,4189 r180 top
U2 "AWR1843AoPBGALP" ALP0180A-MFG 4056.48,4141.13 r180 top
U3 "CP2105-F01-GMR" FP-CP2105-F01-GMR_QFN24-EP-IPC_A 3157.31,4341.42 r0 bottom
U4 "TPS79330DBVR" DBV0005A_N 6882.18,3851.63 r270 bottom
U5 "TMP112AQDRLRQ1" DRL0006A 5312.36,4548.71 r180 bottom
U6 "CAT24C08TDI-GT3" FP-CAT24C08TDI-GT3_TSOT-23-5-IPC_A 5553.54,3840.01 r270 bottom
U7 "BNO085" FP-BNO085_LGA28-MFG 5294.88,3907.22 r270 bottom
U8 "CC2642R1FRGZR" RGZ0048A 6343.38,4111.11 r270 top
U9 "MX25V1635FZNQ" WSON-8L_6x5MM_EP 3170.35,3893.29 r90 bottom locked
U10 "TCA6408ARSVR" RSV0016A 5961.56,3975.2 r270 top
U11 "SN74LVC1G3157DSFR" DSF0006A 6639.32,4040.29 r180 top
U12 "TCAN1042HGVDRBRQ1" DRB0008F 5923.44,4384.46 r90 top
U13 "TS3A5018RSVR" RSV0016A 6728.94,4322.76 r0 top
U14 "TXB0104QRUTRQ1" RUT0012A 6241.04,3825.36 r90 bottom
U15 "TS5A23157RSER" RSE0010A 5654.19,4551.79 r180 top
U16 "SN74LVC1G11DSFR" DSF0006A-MFG 4910.54,4415.28 r180 top
U17 "TCAN1042HGVDRBRQ1" DRB0008F 6799.78,3866 r0 top
U18 "TS5A23157QDGSRQ1" DGS0010A_L 3671.35,4447.33 r270 bottom
U19 "TPS2115ADRBR" DRB0008B 6621.18,3850.46 r0 bottom
Y1 "FW4000044Q" FP-FW4000044Q_4-SMD-2.0x1.6mm-MFG 4130.76,3759.63 r180 top
Y2 "CX2016DB48000C0WPLA2" FP-CX2016DB48000C0WPLA2_SMD4-MFG 6616.71,4189.85 r270 top
Y3 "ABS05W-32.768KHZ-D-2-T" FP-ABS05W-32.768KHZ-D-2-T_XTAL_SMT_1MM6_1MM0-MFG 6320.71,4347.93 r270 top
Y4 "ABS05W-32.768KHZ-D-2-T" FP-ABS05W-32.768KHZ-D-2-T_XTAL_SMT_1MM6_1MM0-MFG 5267.82,3738.88 r0 bottom
ZZ1 "This Assembly Note is for PCB labels only" AssemblyNoteLabel 2349.62,2814.36 r0 top
ZZ2 "These assemblies are ESD sensitive, ESD precautions shall be observed." AssemblyNote 2346.49,2738.89 r0 top
ZZ3 "These assemblies must be clean and free from flux and all contaminants. Use of no clean flux is not acceptable." AssemblyNote 2346.43,2653.5 r0 top
ZZ4 "These assemblies must comply with workmanship standards IPC-A-610 Class 2, unless otherwise specified." AssemblyNote 2343.34,2567.2 r0 top
ZZ5.1 "Cut the thermal pad(Part Number#GPVOUS-0.125-AC-0816) for the shape and size of the inner surface of the heatsink(Part Number#MCH065) and paste it on the inner surface of the heatsink;" AssemblyNote 2340.76,2492.7 r0 top
ZZ5.2 "Bring the heatsink onto the PCB bottom side (Opposite side of AOP device). Match the teeth in the heatsink with break-away area in the PCB and press the heatsink onto the PCB slightly so as thermal pad is spread all over the area" AssemblyNote 2343.41,2409 r0 top

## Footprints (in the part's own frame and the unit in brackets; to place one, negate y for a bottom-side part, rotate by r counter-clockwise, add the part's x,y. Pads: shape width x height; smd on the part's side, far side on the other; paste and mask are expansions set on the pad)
0201L [mm] "Data from Kemet datasheet CC101_COM dated 7/28/11"
  rect 0.36x0.32 smd mask+0: 1(-0.28,0) 2(0.28,0)
0402_070 [mil] "SMD, 2-Leads, Body 1.2x0.7mm, Height 0.7mm"
  rect 15x24 smd: 1(-20,0) 2(20,0)
0402L [mm] "0402 from SM-752 data"
  rect 0.6x0.5 smd: 1(-0.5,0) 2(0.5,0)
0402S [mil] "Based on C0402S footprint from PADS legacy"
  rect 15x24 smd: 1(-20,0) 2(20,0)
0603_HV [mil] "Ernesto recommended land pattern.  26 mil between pads."
  rect 30x30 smd: 1(-28,0) 2(28,0)
  silkscreen extent -52,-24 52,24
0603L [mm] "0603 from SM-752 data"
  rect 0.8x0.85 smd: 1(-0.7,0) 2(0.7,0)
  silkscreen extent -0.07,-0.33 0.07,0.33
0805_HV [mil] "0805 with 30mil clearance between pads"
  rect 50x63 smd: 1(-40,0) 2(40,0)
  silkscreen extent -74,-40 74,40
0805_HV1 [mm] "Custom footprint based on analyzing multiple manufacturer recommendations"
  rrect10% 1x1.25 smd: 1(-1,0) 2(1,0)
  silkscreen extent -0.2,-0.75 0.2,0.75
0805L [mm] "0805 from SM-752 data"
  rect 1.1x1.4 smd: 1(-0.75,0) 2(0.75,0)
ALP0180A-MFG [mm]
  round 0.4 smd paste+0 mask+0: A1(-6.8,6.8) A2(-6,6.8) A3(-5.2,6.8) A4(-4.4,6.8) A5(-3.6,6.8) A6(-2.8,6.8) A7(-2,6.8) A8(-1.2,6.8) A9(-0.4,6.8) A10(0.4,6.8) A11(1.2,6.8) A12(2,6.8) A13(2.8,6.8) A14(3.6,6.8) A15(4.4,6.8) A16(5.2,6.8) A17(6,6.8) A18(6.8,6.8) B1(-6.8,6) B2(-6,6) B3(-5.2,6) B4(-4.4,6) B5(-3.6,6) B6(-2.8,6) B7(-2,6) B8(-1.2,6) B9(-0.4,6) B10(0.4,6) B11(1.2,6) B12(2,6) B13(2.8,6) B14(3.6,6) B15(4.4,6) B16(5.2,6) B17(6,6) B18(6.8,6) C1(-6.8,5.2) C2(-6,5.2) C3(-5.2,5.2) C4(-4.4,5.2) C5(-3.6,5.2) C6(-2.8,5.2) C7(-2,5.2) C8(-1.2,5.2) C9(-0.4,5.2) C10(0.4,5.2) C11(1.2,5.2) C12(2,5.2) C13(2.8,5.2) C14(3.6,5.2) C15(4.4,5.2) C16(5.2,5.2) C17(6,5.2) C18(6.8,5.2) D1(-6.8,4.4) D2(-6,4.4) D3(-5.2,4.4) D16(5.2,4.4) D17(6,4.4) D18(6.8,4.4) E1(-6.8,3.6) E2(-6,3.6) E3(-5.2,3.6) E16(5.2,3.6) E17(6,3.6) E18(6.8,3.6) F1(-6.8,2.8) F2(-6,2.8) F3(-5.2,2.8) F16(5.2,2.8) F17(6,2.8) F18(6.8,2.8) G1(-6.8,2) G2(-6,2) G3(-5.2,2) G16(5.2,2) G17(6,2) G18(6.8,2) H1(-6.8,1.2) H2(-6,1.2) H3(-5.2,1.2) H16(5.2,1.2) H17(6,1.2) H18(6.8,1.2) J1(-6.8,0.4) J2(-6,0.4) J3(-5.2,0.4) J16(5.2,0.4) J17(6,0.4) J18(6.8,0.4) K1(-6.8,-0.4) K2(-6,-0.4) K3(-5.2,-0.4) K16(5.2,-0.4) K17(6,-0.4) K18(6.8,-0.4) L1(-6.8,-1.2) L2(-6,-1.2) L3(-5.2,-1.2) L16(5.2,-1.2) L17(6,-1.2) L18(6.8,-1.2) M1(-6.8,-2) M2(-6,-2) M3(-5.2,-2) M16(5.2,-2) M17(6,-2) M18(6.8,-2) N1(-6.8,-2.8) N2(-6,-2.8) N3(-5.2,-2.8) N16(5.2,-2.8) N17(6,-2.8) N18(6.8,-2.8) P1(-6.8,-3.6) P2(-6,-3.6) P3(-5.2,-3.6) P16(5.2,-3.6) P17(6,-3.6) P18(6.8,-3.6) R1(-6.8,-4.4) R2(-6,-4.4) R3(-5.2,-4.4) R16(5.2,-4.4) R17(6,-4.4) R18(6.8,-4.4) T1(-6.8,-5.2) T2(-6,-5.2) T3(-5.2,-5.2) T4(-4.4,-5.2) T5(-3.6,-5.2) T6(-2.8,-5.2) T7(-2,-5.2) T8(-1.2,-5.2) T9(-0.4,-5.2) T10(0.4,-5.2) T11(1.2,-5.2) T12(2,-5.2) T13(2.8,-5.2) T14(3.6,-5.2) T15(4.4,-5.2) T16(5.2,-5.2) T17(6,-5.2) T18(6.8,-5.2) U1(-6.8,-6) U2(-6,-6) U3(-5.2,-6) U4(-4.4,-6) U5(-3.6,-6) U6(-2.8,-6) U7(-2,-6) U8(-1.2,-6) U9(-0.4,-6) U10(0.4,-6) U11(1.2,-6) U12(2,-6) U13(2.8,-6) U14(3.6,-6) U15(4.4,-6) U16(5.2,-6) U17(6,-6) U18(6.8,-6) V1(-6.8,-6.8) V2(-6,-6.8) V3(-5.2,-6.8) V4(-4.4,-6.8) V5(-3.6,-6.8) V6(-2.8,-6.8) V7(-2,-6.8) V8(-1.2,-6.8) V9(-0.4,-6.8) V10(0.4,-6.8) V11(1.2,-6.8) V12(2,-6.8) V13(2.8,-6.8) V14(3.6,-6.8) V15(4.4,-6.8) V16(5.2,-6.8) V17(6,-6.8) V18(6.8,-6.8)
  silkscreen extent -8.3,-7.55 7.55,7.55
APHHS1005_Green [mm] "SMD, 2-Leads, Body 1x0.5mm"
  rrect20% 0.7x0.5 smd: 1(-0.45,0) 2(0.45,0)
  silkscreen extent -0.8,-0.65 1.12,0.65
AssemblyNote [mil] "Assembly Note"
AssemblyNoteLabel [mil] "Assembly Note for PCB Labels"
BRAKE_WAY_HOLES1X2 [mil]
CONN_105017-0001 [mm] "Molex Micro USB-B"
  rect 0.4x1.35 smd: 1(-1.3,1.35) 2(-0.65,1.35) 3(0,1.35) 4(0.65,1.35) 5(1.3,1.35)
  oval 1.2x1.9 hole 0.6 slot 1.3 at 90 deg: 6(-3.5,-1.35) 9(3.5,-1.35)
  rect 1.5x1.9 smd: 7(-1,-1.35) 8(1,-1.35)
  round 1.45 hole 0.85: 10(2.5,1.35) 11(-2.5,1.35)
  Top Layer region: 3.5,-2.3 2.3,-2.3 2.3,-0.4 3.5,-0.4
  Top Layer region: -3.5,-0.4 -2.3,-0.4 -2.3,-2.3 -3.5,-2.3
  silkscreen extent -4.1,-0.2 4.1,1.4
CUI_PJ-051AH [mm] "DC Power Jack, R/A, TH"
  rrect8% 2.4x1.2 hole 0.8 square: 1(-6.3,3.3) 2(-6.3,-5.3) 3(-6.3,-0.1)
  rrect8% 2.7x1.2 hole 0.8 square: 4(1,-6.2) 5(1,3.7)
  rrect7% 1.5x1.5 hole 1.8 square unplated mask+0: MH1(0,0)
DBV0005A_N [mm] "SOT23, 5-Leads, Body 2.9x1.6mm, Pitch 0.95mm, Lead Span 2.8mm, IPC Medium Density"
  rrect17% 1x0.6 smd: 1(-1.375,0.95) 2(-1.375,0) 3(-1.375,-0.95) 4(1.375,-0.95) 5(1.375,0.95)
  silkscreen extent -0.25,-1.55 0.25,1.55
DFE252012P [mm] "TOKO, Pad sizes increased as per request"
  rect 0.9x2 smd: 1(-1.05,0) 2(1.05,0)
  silkscreen extent -0.3,-1.2 0.3,1.2
DGS0010A_L [mm] "TSSOP, 10-Leads, Body 3x3mm, Pitch 0.5mm, IPC High Density"
  oval 1.15x0.25 smd: 1(-2.125,1) 2(-2.125,0.5) 3(-2.125,0) 4(-2.125,-0.5) 5(-2.125,-1) 6(2.125,-1) 7(2.125,-0.5) 8(2.125,0) 9(2.125,0.5) 10(2.125,1)
  silkscreen extent -2.65,-1.55 0.9,1.55
DRB0008B [mm] "SON, 8-Leads, Body 3x3mm, Pitch 0.65mm, Thermal Pad 2.4x1.65mm, TI Recommended"
  rrect33% 0.6x0.3 smd: 1(-1.4,0.975) 2(-1.4,0.325) 3(-1.4,-0.325) 4(-1.4,-0.975) 5(1.4,-0.975) 6(1.4,-0.325) 7(1.4,0.325) 8(1.4,0.975)
  rrect9% 1.47x1.06 on Bottom Paste: 9(0,-0.63) 9(0,0.63)
  rrect6% 1.65x2.4 smd paste-1.2: 9(0,0)
  silkscreen extent -1.73,-1.73 1.73,1.73
DRB0008F [mm] "SON, 8-Leads, Body 3x3mm, Pitch 0.65mm, Thermal Pad 2.4x1.6mm, TI Recommended"
  rrect33% 0.6x0.3 smd: 1(-1.4,0.975) 2(-1.4,0.325) 3(-1.4,-0.325) 4(-1.4,-0.975) 5(1.4,-0.975) 6(1.4,-0.325) 7(1.4,0.325) 8(1.4,0.975)
  rrect9% 1.47x1.07 on Top Paste: 9(0,0.635) 9(0,-0.635)
  rrect6% 1.6x2.4 smd paste-1.2: 9(0,0)
  silkscreen extent -1.73,-1.73 1.73,1.73
DRL0006A [mm] "SOTFL, 6-Flat Leads, Body 1.2x1.6x0.6mm, Pitch 0.5mm, TI recommended"
  rrect33% 0.67x0.3 smd: 1(-0.74,0.5) 2(-0.74,0) 3(-0.74,-0.5) 4(0.74,-0.5) 5(0.74,0) 6(0.74,0.5)
  silkscreen extent -0.9,-0.95 0.5,0.95
DSF0006A [mm] "TI recommended land pattern"
  rrect59% 0.6x0.17 smd mask+0: 1(-0.4,0.35) 2(-0.4,0) 3(-0.4,-0.35) 4(0.4,-0.35) 5(0.4,0) 6(0.4,0.35)
  silkscreen extent -0.6,-0.63 0.6,0.63
DSF0006A-MFG [mm]
  rrect59% 0.6x0.17 smd paste+0 mask+0: 1(-0.4,0.35) 2(-0.4,0) 3(-0.4,-0.35) 4(0.4,-0.35) 5(0.4,0) 6(0.4,0.35)
  silkscreen extent -1.14,-0.85 0.53,1.02
FIDUCIAL6.4-20 [mil]
  round 25 smd mask+0: 1(0,0)
FP-250R05L120JV4T_0201-IPC_C [mm]
  rrect38% 0.363x0.263 smd paste+0 mask+0: 1(-0.25,0) 2(0.25,0)
FP-4953_HDR1-MFG [mm]
  round 2.5 hole 1.65 paste-1000 mask+0: 1(0,0)
FP-51441-1093_CONN_SMD_FFC-0 [mm]
  rrect33% 0.3x0.65 smd paste+0 mask+0: 1(-2.25,1.775) 2(-1.75,1.775) 3(-1.25,1.775) 4(-0.75,1.775) 5(-0.25,1.775) 6(0.25,1.775) 7(0.75,1.775) 8(1.25,1.775) 9(1.75,1.775) 10(2.25,1.775)
  rrect12% 0.85x1.5 smd paste+0 mask+0: 11(-3.425,-0.75) 12(3.425,-0.75)
FP-ABS05W-32.768KHZ-D-2-T_XTAL_SMT_1MM6_1MM0-MFG [mm]
  rrect20% 0.5x1 smd paste+0 mask+0: 1(-0.55,0) 2(0.55,0)
FP-AC0201FR-0720RL_0201-IPC_C [mil]
  rrect38% 13.94x10.34 smd paste+0 mask+0: 1(-10.01,0) 2(10.01,0)
FP-ANT016008LCS2442MA2_SMT_ANT-0 [mm]
  rrect29% 0.35x0.8 smd paste+0 mask+0: 1(-0.625,0) 4(0.625,0)
  rrect38% 0.6x0.26 smd paste+0 mask+0: 2-3(0,-0.235) 5-6(0,0.235)
FP-BNO085_LGA28-MFG [mm]
  rrect40% 0.675x0.25 smd paste+0 mask+0: 1(1.562,2.25) 6(-1.562,2.25) 7(-1.562,1.75) 8(-1.562,1.25) 9(-1.562,0.75) 10(-1.562,0.25) 11(-1.562,-0.25) 12(-1.562,-0.75) 13(-1.562,-1.25) 14(-1.562,-1.75) 15(-1.562,-2.25) 20(1.562,-2.25) 21(1.562,-1.75) 22(1.562,-1.25) 23(1.562,-0.75) 24(1.562,-0.25) 25(1.562,0.25) 26(1.562,0.75) 27(1.562,1.25) 28(1.562,1.75)
  rrect40% 0.25x0.575 smd paste+0 mask+0: 2(0.75,2.312) 3(0.25,2.312) 4(-0.25,2.312) 5(-0.75,2.312) 16(-0.75,-2.312) 17(-0.25,-2.312) 18(0.25,-2.312) 19(0.75,-2.312)
FP-BSS123-7-F_SOT23-IPC_C [mm]
  rrect18% 1.059x0.547 smd paste+0 mask+0: 1(-0.877,0.915)
  rrect100% 1.059x0.547 smd paste+0 mask+0: 2(-0.877,-0.915) 3(0.877,0)
FP-CAT24C08TDI-GT3_TSOT-23-5-IPC_A [mm]
  rrect18% 1.54x0.566 smd paste+0 mask+0: 1(-1.216,0.95)
  rrect100% 1.54x0.566 smd paste+0 mask+0: 2(-1.216,0) 3(-1.216,-0.95) 4(1.216,-0.95) 5(1.216,0.95)
FP-CGA1A2C0G1H4R7C030BA_0201-IPC_C [mil]
  rrect35% 11.14x12.52 smd paste+0 mask+0: 1(-12.5,0) 2(12.5,0)
  silkscreen extent -18,-24 18,14
FP-CGA4J1X7T0J226M125AC_0805-MFG [mm]
  rrect13% 0.8x1.05 smd paste+0 mask+0: 1(-0.925,0) 2(0.925,0)
  silkscreen extent -0.15,-0.77 0.15,0.77
FP-CHS-01TA_SMT_SW_5MM4_2MM5-MFG [mm]
  rrect10% 1.6x1 smd paste+0 mask+0: 1(-2.54,0) 2(2.54,0)
FP-CL03A103KA3NNNC_0201-IPC_C [mil]
  rrect38% 13.94x10.34 smd paste+0 mask+0: 1(-10.01,0) 2(10.01,0)
FP-CL03A105MO3NRNH_0201-IPC_C [mil]
  rrect33% 15.83x11.94 smd paste+0 mask+0: 1(-9.87,0) 2(9.87,0)
FP-CP2105-F01-GMR_QFN24-EP-IPC_A [mm]
  rrect42% 0.979x0.239 smd paste+0 mask+0: 1(-1.99,1.25)
  rrect100% 0.979x0.239 smd paste+0 mask+0: 2(-1.99,0.75) 3(-1.99,0.25) 4(-1.99,-0.25) 5(-1.99,-0.75) 6(-1.99,-1.25) 13(1.99,-1.25) 14(1.99,-0.75) 15(1.99,-0.25) 16(1.99,0.25) 17(1.99,0.75) 18(1.99,1.25)
  rrect100% 0.239x0.979 smd paste+0 mask+0: 7(-1.25,-1.99) 8(-0.75,-1.99) 9(-0.25,-1.99) 10(0.25,-1.99) 11(0.75,-1.99) 12(1.25,-1.99) 19(1.25,1.99) 20(0.75,1.99) 21(0.25,1.99) 22(-0.25,1.99) 23(-0.75,1.99) 24(-1.25,1.99)
  rrect4% 2.7x2.7 smd paste-1000 mask+0: 25(0,0)
FP-CRCW0402200RFKEDHP_0402-IPC_C [mil]
  rrect21% 20.29x18.6 smd paste+0 mask+0: 1(-14.9,0) 2(14.9,0)
FP-CX2016DB48000C0WPLA2_SMD4-MFG [mm]
  rrect13% 0.9x0.8 smd paste+0 mask+0: 1(-0.7,-0.55) 2(0.7,-0.55) 3(0.7,0.55) 4(-0.7,0.55)
  silkscreen extent -1.9,-1.35 1.05,1.35
FP-ERA-1AEB103C_0201-IPC_C [mil]
  rrect38% 13.94x10.34 smd paste+0 mask+0: 1(-10.01,0) 2(10.01,0)
  silkscreen extent -17,-22 17,22
FP-ERJ-1GNF33R2C_0201-IPC_C [mil]
  rrect38% 13.94x10.34 smd paste+0 mask+0: 1(-10.01,0) 2(10.01,0)
  silkscreen extent -17,-22 17,22
FP-ERJ-1GNF1003C_0201-IPC_C [mil]
  rrect38% 13.94x10.34 smd paste+0 mask+0: 1(-10.01,0) 2(10.01,0)
  silkscreen extent -17,-22 17,22
FP-ERJ-1GNF1961C_0201-IPC_C [mil]
  rrect38% 13.94x10.34 smd paste+0 mask+0: 1(-10.01,0) 2(10.01,0)
  silkscreen extent -17,-22 17,22
FP-ERJ-1GNF4701C_0201-IPC_C [mil]
  rrect38% 13.94x10.34 smd paste+0 mask+0: 1(-10.01,0) 2(10.01,0)
FP-ERJ-1GNF4991C_0201-IPC_C [mil]
  rrect38% 13.94x10.34 smd paste+0 mask+0: 1(-10.01,0) 2(10.01,0)
  silkscreen extent -17,-22 17,12
FP-ERJ-1GNF7871C_0201-IPC_C [mil]
  rrect38% 13.94x10.34 smd paste+0 mask+0: 1(-10.01,0) 2(10.01,0)
  silkscreen extent -17,-12 17,12
FP-ERJ-1GNF8252C_0201-IPC_C [mil]
  rrect38% 13.94x10.34 smd paste+0 mask+0: 1(-10.01,0) 2(10.01,0)
  silkscreen extent -17,-12 17,12
FP-ERJ-1GNJ102C_0201-IPC_C [mil]
  rrect38% 13.94x10.34 smd paste+0 mask+0: 1(-10.01,0) 2(10.01,0)
  silkscreen extent -17,-22 17,22
FP-ERJ-1GNJ221C_0201-IPC_C [mil]
  rrect38% 13.94x10.34 smd paste+0 mask+0: 1(-10.01,0) 2(10.01,0)
  silkscreen extent -17,-22 17,22
FP-ERJ-1GNJ511C_0201-IPC_C [mil]
  rrect38% 13.94x10.34 smd paste+0 mask+0: 1(-10.01,0) 2(10.01,0)
  silkscreen extent -17,-22 17,22
FP-ERJ-1GNJ751C_0201-IPC_C [mil]
  rrect38% 13.94x10.34 smd paste+0 mask+0: 1(-10.01,0) 2(10.01,0)
  silkscreen extent -17,-12 17,12
FP-EXB-18VR000X_0502-MFG [mm]
  rrect57% 0.175x0.3 smd paste+0 mask+0: 1(-0.6,-0.275) 2(-0.2,-0.275) 3(0.2,-0.275) 4(0.6,-0.275) 5(0.6,0.275) 6(0.2,0.275) 7(-0.2,0.275) 8(-0.6,0.275)
FP-FW4000044Q_4-SMD-2.0x1.6mm-MFG [mm]
  rrect13% 0.9x0.8 smd paste+0 mask+0: 1(-0.7,-0.55) 2(0.7,-0.55) 3(0.7,0.55) 4(-0.7,0.55)
  silkscreen extent -1.83,-1.1 1,1.35
"FP-GRM033R6YA104KE14D_0201 (0603 Metric)-IPC_C" [mil]
  rrect38% 13.94x10.34 smd paste+0 mask+0: 1(-10.01,0) 2(10.01,0)
"FP-GRM0335C1H8R0BA01D_0201 (0603 metric)-IPC_C" [mil]
  rrect38% 13.94x10.34 smd paste+0 mask+0: 1(-10.01,0) 2(10.01,0)
FP-GRPB052MWCN-RC_HDR10-MFG [mm]
  rrect9% 1.12x1.12 hole 0.7 paste-1000 mask+0: 1(-2.54,1.15)
  round 1.12 hole 0.7 paste-1000 mask+0: 2(-2.54,2.42) 3(-1.27,1.15) 4(-1.27,2.42) 5(0,1.15) 6(0,2.42) 7(1.27,1.15) 8(1.27,2.42) 9(2.54,1.15) 10(2.54,2.42)
  silkscreen extent -3.77,-0.7 3.42,1.17
FP-M50-3930342_HDR3-MFG [mm]
  rrect9% 1.1x1.1 hole 0.6 paste-1000 mask+0: 1(-1.27,1)
  round 1.1 hole 0.6 paste-1000 mask+0: 2(0,1) 3(1.27,1)
  silkscreen extent -2.15,-0.6 2.15,2.09
FP-M50-3930442_HDR4-RECOMMENDED_LAND_PATTERN [mm]
  rrect9% 1.1x1.1 hole 0.6 paste-1000 mask+0: 1(-1.905,1)
  round 1.1 hole 0.6 paste-1000 mask+0: 2(-0.635,1) 3(0.635,1) 4(1.905,1)
FP-MPZ2012S101ATD25_0805-MFG [mm]
  rrect13% 0.8x1.2 smd paste+0 mask+0: 1(-0.9,0) 2(0.9,0)
  silkscreen extent -0.13,-0.72 0.13,0.72
FP-NRVB230LSFT1G_SOD-123F-MFG [mm]
  rrect8% 1.25x1.22 smd paste+0 mask+0: 1(-1.475,0) 2(1.475,0)
  silkscreen extent -2.8,-0.9 0.48,0.9
"FP-RC0201JR-070RL_0201 (0603 Metric)-IPC_C" [mil]
  rrect38% 13.94x10.34 smd paste+0 mask+0: 1(-10.01,0) 2(10.01,0)
"FP-RC0201JR-070RL_0201 (0603 METRIC)-IPC_C" [mil]
  rrect38% 13.94x10.34 smd paste+0 mask+0: 1(-10.01,0) 2(10.01,0)
"FP-RC0201JR-070RL_0201 (0603 Metric)-MFG" [mm]
  rrect29% 0.35x0.4 smd paste+0 mask+0: 1(-0.325,0) 2(0.325,0)
FP-RR0306P-103-D_0201-IPC_C#1 [mil]
  rrect37% 13.31x10.73 smd paste+0 mask+0: 1(-10.52,0) 2(10.52,0)
FP-RR0306P-103-D_0201-IPC_C#2 [mil]
  rrect38% 13.94x10.34 smd paste+0 mask+0: 1(-10.52,0)
  rrect37% 13.31x10.73 smd paste+0 mask+0: 2(10.52,0)
IND_LQG15H [mm] "MuRata"
  rect 0.55x0.6 smd: 1(-0.475,0) 2(0.475,0)
  silkscreen extent -1.3,-0.3 -0.95,0.3
MHNP_2-5 [mil]
  round 95 hole 100 unplated mask+0: ""(0,0)
  Keep-Out Layer circle w1: c0,0 r100
MHNP_M2_PANHEAD_PHILLIPS [mil]
  round 83 hole 88 unplated mask+0: ""(0,0)
  Keep-Out Layer circle w1: c0,0 r88
RGZ0048A [mm] "VQFN-48"
  rrect42% 0.6x0.24 smd: 1(-3.4,2.75) 2(-3.4,2.25) 3(-3.4,1.75) 4(-3.4,1.25) 5(-3.4,0.75) 6(-3.4,0.25) 7(-3.4,-0.25) 8(-3.4,-0.75) 9(-3.4,-1.25) 10(-3.4,-1.75) 11(-3.4,-2.25) 12(-3.4,-2.75) 25(3.4,-2.75) 26(3.4,-2.25) 27(3.4,-1.75) 28(3.4,-1.25) 29(3.4,-0.75) 30(3.4,-0.25) 31(3.4,0.25) 32(3.4,0.75) 33(3.4,1.25) 34(3.4,1.75) 35(3.4,2.25) 36(3.4,2.75)
  rrect42% 0.24x0.6 smd: 13(-2.75,-3.4) 14(-2.25,-3.4) 15(-1.75,-3.4) 16(-1.25,-3.4) 17(-0.75,-3.4) 18(-0.25,-3.4) 19(0.25,-3.4) 20(0.75,-3.4) 21(1.25,-3.4) 22(1.75,-3.4) 23(2.25,-3.4) 24(2.75,-3.4) 37(2.75,3.4) 38(2.25,3.4) 39(1.75,3.4) 40(1.25,3.4) 41(0.75,3.4) 42(0.25,3.4) 43(-0.25,3.4) 44(-0.75,3.4) 45(-1.25,3.4) 46(-1.75,3.4) 47(-2.25,3.4) 48(-2.75,3.4)
  rrect2% 5.15x5.15 smd paste-2.6: 49(0,0)
RNF0026C [mm] "QFN, 26-Leads, Body 4x4.5mm, Pitch 0.5mm"
  rrect25% 0.6x0.4 smd paste-0.3: 1(-1.9,1.825) 8(-1.9,-1.825) 14(1.9,-1.825) 21(1.9,1.825)
  rrect40% 0.6x0.25 smd paste+0: 2(-1.9,1.25) 3(-1.9,0.75) 4(-1.9,0.25) 5(-1.9,-0.25) 6(-1.9,-0.75) 7(-1.9,-1.25) 15(1.9,-1.25) 16(1.9,-0.75) 17(1.9,-0.25) 18(1.9,0.25) 19(1.9,0.75) 20(1.9,1.25)
  rrect40% 0.25x1.82 smd paste-1: 9(-1,-1.54) 10(-0.5,-1.54) 11(0,-1.54) 12(0.5,-1.54) 13(1,-1.54) 22(1,1.54) 23(0.5,1.54) 24(0,1.54) 25(-0.5,1.54) 26(-1,1.54)
  rrect15% 2.24x0.66 smd paste-1: 27(0,0)
  rrect33% 0.6x0.3 on Top Paste: ""(-1.9,1.775) ""(-1.9,-1.775) ""(1.9,1.775) ""(1.9,-1.775)
  rrect33% 0.3x0.825 on Top Paste: ""(-1.575,2.037) ""(-1.575,-2.037) ""(1.575,2.037) ""(1.575,-2.037)
  rrect40% 0.25x0.81 on Top Paste: ""(-1,1.035) ""(-1,2.045) ""(-1,-2.045) ""(-1,-1.035) ""(-0.5,2.045) ""(-0.5,1.035) ""(-0.5,-1.035) ""(-0.5,-2.045) ""(0,2.045) ""(0,1.035) ""(0,-1.035) ""(0,-2.045) ""(0.5,2.045) ""(0.5,1.035) ""(0.5,-1.035) ""(0.5,-2.045) ""(1,1.035) ""(1,2.045) ""(1,-2.045) ""(1,-1.035)
  rrect15% 0.98x0.66 on Top Paste: ""(-0.59,0) ""(0.59,0)
  silkscreen extent -2.45,-2.7 2.45,2.7
RSE0010A [mm] "QFN, 10-Leads, Body 1.5x2mm, Pitch 0.5mm, TI Recommended"
  rect 0.55x0.2 smd: 1(-0.675,0.75) 2(-0.675,0.25) 3(-0.675,-0.25) 4(-0.675,-0.75) 6(0.675,-0.75) 7(0.675,-0.25) 8(0.675,0.25) 9(0.675,0.75)
  rect 0.3x0.6 smd: 5(0,-0.9) 10(0,0.9)
  silkscreen extent -1.07,-1.17 0.77,1.18
RSV0016A [mm] "QFN, 16-Leads, Body 1.8x2.6mm, Pitch 0.4mm, TI Recommended"
  rect 0.7x0.2 smd: 1(-0.75,0.6)
  rect 0.6x0.2 smd: 2(-0.8,0.2) 3(-0.8,-0.2) 4(-0.8,-0.6) 9(0.8,-0.6) 10(0.8,-0.2) 11(0.8,0.2) 12(0.8,0.6)
  rect 0.2x0.6 smd: 5(-0.6,-1.2) 6(-0.2,-1.2) 7(0.2,-1.2) 8(0.6,-1.2) 13(0.6,1.2) 14(0.2,1.2) 15(-0.2,1.2) 16(-0.6,1.2)
  silkscreen extent -1.08,-1.33 1.08,1.45
RUT0012A [mm] "QFN, 12-Leads, Body 1.7x2mm, Pitch 0.4mm, TI Recommended"
  rrect50% 0.7x0.2 smd: 1(-0.7,0.8) 2(-0.7,0.4) 3(-0.7,0) 4(-0.7,-0.4) 5(-0.7,-0.8) 7(0.7,-0.8) 8(0.7,-0.4) 9(0.7,0) 10(0.7,0.4) 11(0.7,0.8)
  rrect50% 0.2x0.7 smd: 6(0,-0.85) 12(0,0.85)
  silkscreen extent -0.9,-1.2 0.9,1.2
Samtec_QSH-030-01-X-D-A [mm] "Receptacle, 0.5 mm, 30x2, TH"
  rect 2.27x0.279 smd: 1(-2.865,7.25) 2(2.865,7.25) 3(-2.865,6.75) 4(2.865,6.75) 5(-2.865,6.25) 6(2.865,6.25) 7(-2.865,5.75) 8(2.865,5.75) 9(-2.865,5.25) 10(2.865,5.25) 11(-2.865,4.75) 12(2.865,4.75) 13(-2.865,4.25) 14(2.865,4.25) 15(-2.865,3.75) 16(2.865,3.75) 17(-2.865,3.25) 18(2.865,3.25) 19(-2.865,2.75) 20(2.865,2.75) 21(-2.865,2.25) 22(2.865,2.25) 23(-2.865,1.75) 24(2.865,1.75) 25(-2.865,1.25) 26(2.865,1.25) 27(-2.865,0.75) 28(2.865,0.75) 29(-2.865,0.25) 30(2.865,0.25) 31(-2.865,-0.25) 32(2.865,-0.25) 33(-2.865,-0.75) 34(2.865,-0.75) 35(-2.865,-1.25) 36(2.865,-1.25) 37(-2.865,-1.75) 38(2.865,-1.75) 39(-2.865,-2.25) 40(2.865,-2.25) 41(-2.865,-2.75) 42(2.865,-2.75) 43(-2.865,-3.25) 44(2.865,-3.25) 45(-2.865,-3.75) 46(2.865,-3.75) 47(-2.865,-4.25) 48(2.865,-4.25) 49(-2.865,-4.75) 50(2.865,-4.75) 51(-2.865,-5.25) 52(2.865,-5.25) 53(-2.865,-5.75) 54(2.865,-5.75) 55(-2.865,-6.25) 56(2.865,-6.25) 57(-2.865,-6.75) 58(2.865,-6.75) 59(-2.865,-7.25) 60(2.865,-7.25)
  round 0 hole 1.02 unplated: MH1(2.67,10.065) MH2(2.67,-10.065)
  rect 0.43x2.54 smd: MP1(0,8.065) MP4(0,-8.065)
  rect 0.43x4.7 smd: MP2(0,3.175) MP3(0,-3.175)
  silkscreen extent -3.9,-10.66 3.62,10.66
SW_218-4LPST [mil] "CTS Components"
  rect 50x30 smd: 1(-150,75) 2(-150,25) 3(-150,-25) 4(-150,-75) 5(150,-75) 6(150,-25) 7(150,25) 8(150,75)
  silkscreen extent -114,-123 114,123
SW_B3U-1000P [mm] "OMRON"
  rect 0.8x1.7 smd: 1(-1.7,0) 2(1.7,0)
  silkscreen extent -1.5,-1.25 1.5,1.25
TP_25MIL-SMT [mil]
  round 25 smd mask+0: 1(0,0)
TP_SM_1MM [mm] "1mm Test Point, SMT"
  round 1 smd paste-0.5: 1(0,0)
TP_VIA_060RND040 [mil] "TP_VIA_060RND040"
  round 60 hole 40: 1(0,0)
WSON-8L_6x5MM_EP [mm] "SMD, 8-Leads, Body 6x5mm, Pitch 1.27mm"
  rrect25% 0.8x0.4 smd: 1(-2.8,1.905) 2(-2.8,0.635) 3(-2.8,-0.635) 4(-2.8,-1.905) 5(2.8,-1.905) 6(2.8,-0.635) 7(2.8,0.635) 8(2.8,1.905)
  rrect3% 3.4x4 smd paste-3: 9(0,0)
  rrect50% 1.468x1.698 on Bottom Paste: ""(-0.834,-0.949) ""(-0.834,0.949) ""(0.834,-0.949) ""(0.834,0.949)
  silkscreen extent -3.2,-2.7 3.2,2.7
